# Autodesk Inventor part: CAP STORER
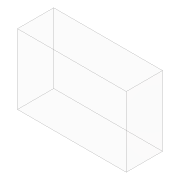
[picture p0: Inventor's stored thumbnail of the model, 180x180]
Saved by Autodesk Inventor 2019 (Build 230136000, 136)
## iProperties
Created: 2019-10
Part Number: CAP STORER
Material: PET Plastic
Document SubType Name: Modeling
Designer: hp
Density: 1.541 g/cm^3
Appearance: Polycarbonate - Clear
Author: hp
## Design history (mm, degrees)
sketch "Sketch1"
  geometry: L1 (129.887, 60.091)-(-80.113, 60.091); L2 (-80.113, 60.091)-(-80.113, -74.909); L3 (-80.113, -74.909)-(129.887, -74.909); L4 (129.887, -74.909)-(129.887, 60.091); 1 further point
  constraints: 8 end point, 2 parallel, 1 horizontal, 1 perpendicular
  dimensions: "d8" = 210 distance of L3.end L2.end; "d9" = 135 distance of L2.end L1.end
extrude "Extrusion1" new body sketch "Sketch1" distance "d2" = 70; taper "d3" = 0 deg
body "Solid1"
